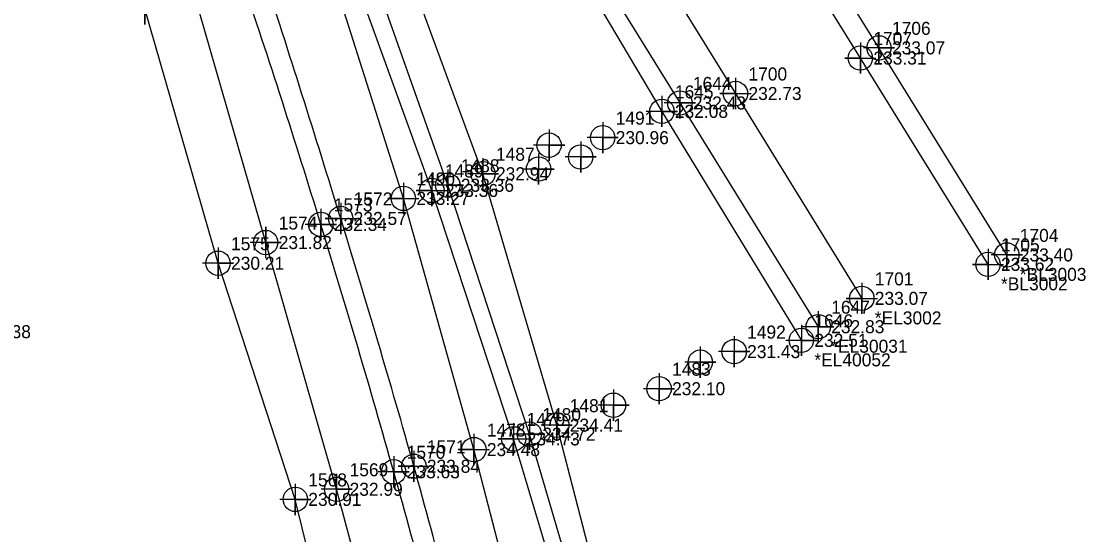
# Model space of a CAD drawing. Extents: x 2130962 to 2131465, y 643052 to 644206.
# Drawn here: x 2131080.2 to 2131285, y 643795.8 to 643894.5 of the extents above; entities that cross this region are included whole.
import ezdxf

# ---------------------------------------------------------------- set-up
doc = ezdxf.new("R2010")
doc.units = 0
for name, color, linetype in [('Exist DTM Breakline', 7, 'Continuous'), ('Exist DTM Breakline Cogo Comment', 7, 'Continuous'), ('Exist DTM Breakline Cogo Elevation', 7, 'Continuous'), ('Exist DTM Breakline Cogo Number', 7, 'Continuous'), ('Exist DTM Breakline Cogo Point CELL', 7, 'Continuous'), ('Exist DTM Drainline', 7, 'Continuous'), ('Exist DTM Drainline Cogo Elevation', 7, 'Continuous'), ('Exist DTM Drainline Cogo Number', 7, 'Continuous'), ('Exist DTM Drainline Cogo Point CELL', 7, 'Continuous'), ('Exist DTM Regular Point CELL', 7, 'Continuous'), ('Exist DTM Regular Point Cogo Elevation', 7, 'Continuous'), ('Exist DTM Regular Point Cogo Number', 7, 'Continuous'), ('Exist Roads EOP', 7, 'Continuous'), ('Exist Roads EOP Cogo Elevation', 7, 'Continuous'), ('Exist Roads EOP Cogo Number', 7, 'Continuous'), ('Exist Roads EOP Cogo Point CELL', 7, 'Continuous'), ('Exist Roads EOP Other Cogo Comment', 7, 'Continuous'), ('Exist Roads EOP Other Cogo Elevation', 7, 'Continuous'), ('Exist Roads EOP Other Cogo Number', 7, 'Continuous'), ('Exist Roads EOP Other Cogo Point CELL', 7, 'Continuous'), ('Exist Roads EOT', 7, 'Continuous'), ('Exist Roads EOT Cogo Comment', 7, 'Continuous'), ('Exist Roads EOT Cogo Elevation', 7, 'Continuous'), ('Exist Roads EOT Cogo Number', 7, 'Continuous'), ('Exist Roads EOT Cogo Point CELL', 7, 'Continuous'), ('Exist Roads Soil', 7, 'Continuous'), ('Exist Roads Soil Cogo Elevation', 7, 'Continuous'), ('Exist Roads Soil Cogo Number', 7, 'Continuous'), ('Exist Roads Soil Cogo Point CELL', 7, 'Continuous')]:
    doc.layers.add(name, color=color, linetype=linetype)

msp = doc.modelspace()

# ---------------------------------------------------------------- linework, layer by layer
at = {"layer": 'Exist DTM Breakline'}
for points in [[(2131266.3306, 643269.372), (2131264.0776, 643319.4437), (2131258.8396, 643369.5498), (2131255.3671, 643419.5794), (2131249.6414, 643469.556), (2131244.7652, 643520.0623), (2131238.8778, 643569.4077), (2131228.6495, 643620.6699), (2131219.85, 643669.4823), (2131206.9682, 643717.8453), (2131195.8132, 643768.1497), (2131183.2404, 643816.8151), (2131169.0496, 643865.1461), (2131151.2314, 643913.4424), (2131130.7295, 643958.9736), (2131122.7411, 643983.0115)], [(2131150.4586, 643966.3443), (2131176.896, 643921.8304), (2131203.4733, 643877.1362), (2131230.3046, 643833.1199)]]:
    msp.add_lwpolyline(points, dxfattribs=at)
at = {"layer": 'Exist DTM Breakline Cogo Point CELL'}
for points in [[(2131203.4733, 643880.1362), (2131203.4733, 643874.1362), (2131203.4733, 643877.1362), (2131206.4733, 643877.1362), (2131200.4733, 643877.1362)], [(2131169.0496, 643868.1461), (2131169.0496, 643862.1461), (2131169.0496, 643865.1461), (2131172.0496, 643865.1461), (2131166.0496, 643865.1461)], [(2131230.3046, 643836.1199), (2131230.3046, 643830.1199), (2131230.3046, 643833.1199), (2131233.3046, 643833.1199), (2131227.3046, 643833.1199)], [(2131183.2404, 643819.8151), (2131183.2404, 643813.8151), (2131183.2404, 643816.8151), (2131186.2404, 643816.8151), (2131180.2404, 643816.8151)]]:
    msp.add_lwpolyline(points, dxfattribs=at)
for centre in [(2131203.4733, 643877.1362), (2131169.0496, 643865.1461), (2131230.3046, 643833.1199), (2131183.2404, 643816.8151)]:
    msp.add_circle(centre, 2.344, dxfattribs=at)
at = {"layer": 'Exist DTM Drainline'}
msp.add_lwpolyline([(2131000.2029, 643226.7228), (2131050.9884, 643228.9032), (2131099.0297, 643228.5605), (2131120.2968, 643239.3591), (2131144.9156, 643253.3469), (2131146.4739, 643252.3674), (2131154.3188, 643256.8046), (2131168.9618, 643265.5132), (2131176.6257, 643272.964), (2131179.8144, 643285.303), (2131183.3842, 643315.022), (2131190.1471, 643365.8731), (2131190.1489, 643413.686), (2131192.3886, 643466.4632), (2131188.8083, 643512.615), (2131184.0059, 643563.7066), (2131175.3, 643610.7482), (2131168.3784, 643658.7431), (2131156.7476, 643707.4708), (2131144.9036, 643754.0458), (2131132.9438, 643802.544), (2131118.0831, 643847.9475), (2131104.0084, 643896.8663), (2131096.3866, 643919.4077)], dxfattribs=at)
at = {"layer": 'Exist DTM Drainline Cogo Point CELL'}
for points in [[(2131104.0084, 643899.8663), (2131104.0084, 643893.8663), (2131104.0084, 643896.8663), (2131107.0084, 643896.8663), (2131101.0084, 643896.8663)], [(2131118.0831, 643850.9475), (2131118.0831, 643844.9475), (2131118.0831, 643847.9475), (2131121.0831, 643847.9475), (2131115.0831, 643847.9475)], [(2131132.9438, 643805.544), (2131132.9438, 643799.544), (2131132.9438, 643802.544), (2131135.9438, 643802.544), (2131129.9438, 643802.544)]]:
    msp.add_lwpolyline(points, dxfattribs=at)
for centre in [(2131118.0831, 643847.9475), (2131132.9438, 643802.544)]:
    msp.add_circle(centre, 2.344, dxfattribs=at)
at = {"layer": 'Exist DTM Regular Point CELL'}
for points in [[(2131192.0852, 643875.0907), (2131192.0852, 643869.0907), (2131192.0852, 643872.0907), (2131195.0852, 643872.0907), (2131189.0852, 643872.0907)], [(2131181.7718, 643873.64), (2131181.7718, 643867.64), (2131181.7718, 643870.64), (2131184.7718, 643870.64), (2131178.7718, 643870.64)], [(2131187.8499, 643871.3759), (2131187.8499, 643865.3759), (2131187.8499, 643868.3759), (2131190.8499, 643868.3759), (2131184.8499, 643868.3759)], [(2131179.7469, 643869.0572), (2131179.7469, 643863.0572), (2131179.7469, 643866.0572), (2131182.7469, 643866.0572), (2131176.7469, 643866.0572)], [(2131217.3691, 643833.9559), (2131217.3691, 643827.9559), (2131217.3691, 643830.9559), (2131220.3691, 643830.9559), (2131214.3691, 643830.9559)], [(2131210.8569, 643831.9342), (2131210.8569, 643825.9342), (2131210.8569, 643828.9342), (2131213.8569, 643828.9342), (2131207.8569, 643828.9342)], [(2131202.9275, 643826.8229), (2131202.9275, 643820.8229), (2131202.9275, 643823.8229), (2131205.9275, 643823.8229), (2131199.9275, 643823.8229)], [(2131194.1553, 643823.6479), (2131194.1553, 643817.6479), (2131194.1553, 643820.6479), (2131197.1553, 643820.6479), (2131191.1553, 643820.6479)]]:
    msp.add_lwpolyline(points, dxfattribs=at)
for centre in [(2131181.7718, 643870.64), (2131192.0852, 643872.0907), (2131187.8499, 643868.3759), (2131179.7469, 643866.0572), (2131217.3691, 643830.9559), (2131210.8569, 643828.9342), (2131202.9275, 643823.8229), (2131194.1553, 643820.6479)]:
    msp.add_circle(centre, 2.344, dxfattribs=at)
at = {"layer": 'Exist Roads EOP'}
for points in [[(2131269.8281, 643849.5438), (2131245.2333, 643889.3452), (2131216.1751, 643936.1301), (2131188.6585, 643980.6301), (2131160.5575, 644026.0233), (2131133.7706, 644069.3844), (2131106.5621, 644113.2921), (2131078.4587, 644158.6941), (2131052.1516, 644201.1049)], [(2131124.9979, 644001.4036), (2131151.4846, 643966.5856), (2131158.5905, 643957.1022), (2131179.4402, 643923.1833), (2131206.9257, 643878.7542), (2131233.5521, 643835.7453)], [(2131264.2715, 643222.5647), (2131259.8757, 643269.3254), (2131257.0196, 643319.4043), (2131254.2561, 643369.6499), (2131250.0777, 643419.4187), (2131246.1511, 643469.0294), (2131240.8382, 643519.1271), (2131234.3674, 643568.5584), (2131226.3321, 643620.1808), (2131217.0271, 643668.7116), (2131205.6213, 643717.607), (2131192.0578, 643767.2595), (2131177.9714, 643815.0911), (2131162.2913, 643862.9344), (2131145.3604, 643910.8486), (2131126.9113, 643957.2915), (2131112.3691, 643996.1228)]]:
    msp.add_lwpolyline(points, dxfattribs=at)
msp.add_spline([(2131166.2495, 643216.6951), (2131171.8131, 643218.7244), (2131182.3713, 643223.9726), (2131191.8117, 643231.1489), (2131200.5013, 643239.6993), (2131208.8071, 643249.0697), (2131216.0672, 643259.0032), (2131218.7188, 643264.347), (2131220.5363, 643270.0958), (2131222.8445, 643282.0077), (2131224.3583, 643293.9245), (2131224.8763, 643317.7904), (2131222.0632, 643367.6716), (2131218.5448, 643416.8114), (2131214.3187, 643466.3462), (2131209.1735, 643515.6666), (2131202.7939, 643565.1545), (2131195.0475, 643613.9937), (2131186.4014, 643662.4763), (2131176.0113, 643711.405), (2131164.6154, 643759.8896), (2131151.874, 643807.8526), (2131137.8554, 643855.4065), (2131122.5733, 643902.8574), (2131105.9622, 643949.4862), (2131091.5349, 643988.0437)], degree=3, dxfattribs=at)
at = {"layer": 'Exist Roads EOP Cogo Point CELL'}
for points in [[(2131162.2913, 643865.9344), (2131162.2913, 643859.9344), (2131162.2913, 643862.9344), (2131165.2913, 643862.9344), (2131159.2913, 643862.9344)], [(2131137.8554, 643858.4065), (2131137.8554, 643852.4065), (2131137.8554, 643855.4065), (2131140.8554, 643855.4065), (2131134.8554, 643855.4065)], [(2131177.9714, 643818.0911), (2131177.9714, 643812.0911), (2131177.9714, 643815.0911), (2131180.9714, 643815.0911), (2131174.9714, 643815.0911)], [(2131151.874, 643810.8526), (2131151.874, 643804.8526), (2131151.874, 643807.8526), (2131154.874, 643807.8526), (2131148.874, 643807.8526)]]:
    msp.add_lwpolyline(points, dxfattribs=at)
for centre in [(2131162.2913, 643862.9344), (2131137.8554, 643855.4065), (2131177.9714, 643815.0911), (2131151.874, 643807.8526)]:
    msp.add_circle(centre, 2.344, dxfattribs=at)
at = {"layer": 'Exist Roads EOP Other Cogo Point CELL'}
for points in [[(2131245.2333, 643892.3452), (2131245.2333, 643886.3452), (2131245.2333, 643889.3452), (2131248.2333, 643889.3452), (2131242.2333, 643889.3452)], [(2131206.9257, 643881.7542), (2131206.9257, 643875.7542), (2131206.9257, 643878.7542), (2131209.9257, 643878.7542), (2131203.9257, 643878.7542)], [(2131269.8281, 643852.5438), (2131269.8281, 643846.5438), (2131269.8281, 643849.5438), (2131272.8281, 643849.5438), (2131266.8281, 643849.5438)], [(2131233.5521, 643838.7453), (2131233.5521, 643832.7453), (2131233.5521, 643835.7453), (2131236.5521, 643835.7453), (2131230.5521, 643835.7453)]]:
    msp.add_lwpolyline(points, dxfattribs=at)
for centre in [(2131245.2333, 643889.3452), (2131206.9257, 643878.7542), (2131269.8281, 643849.5438), (2131233.5521, 643835.7453)]:
    msp.add_circle(centre, 2.344, dxfattribs=at)
at = {"layer": 'Exist Roads EOT'}
for points in [[(2131266.2139, 643847.7337), (2131241.6557, 643887.3896), (2131212.415, 643934.4728), (2131185.0265, 643979.1763), (2131157.0131, 644024.017), (2131130.1473, 644067.7247), (2131102.8992, 644111.8313), (2131074.9921, 644156.7275), (2131048.5158, 644199.6357)], [(2131027.1782, 644188.3908), (2131054.4288, 644144.4752), (2131080.5567, 644102.0812), (2131108.007, 644057.7457), (2131134.6373, 644014.7205), (2131162.4421, 643969.638), (2131189.8746, 643925.4695), (2131217.6277, 643880.5724), (2131241.9317, 643841.1922)], [(2131255.7894, 643269.2666), (2131252.7511, 643319.2443), (2131249.9083, 643369.5477), (2131246.3502, 643419.1778), (2131242.1933, 643468.6938), (2131237.0867, 643518.9193), (2131230.8671, 643568.2588), (2131222.7066, 643619.1047), (2131213.6442, 643668.3078), (2131202.755, 643717.0933), (2131189.234, 643766.4577), (2131174.9499, 643814.1787), (2131159.2111, 643861.933), (2131141.9103, 643909.6722), (2131123.7008, 643956.0828), (2131104.9436, 644003.1503), (2131086.2706, 644048.8072), (2131065.6997, 644094.9191), (2131044.3618, 644140.0645), (2131021.6804, 644185.4526)], [(2131237.6994, 643363.706), (2131234.1644, 643418.0043), (2131229.8934, 643468.0098), (2131225.1139, 643518.3873), (2131218.7748, 643566.6133), (2131210.7043, 643617.3811), (2131201.4139, 643666.7928), (2131191.4121, 643714.0755), (2131179.6696, 643764.3904), (2131167.3006, 643812.1237), (2131153.7359, 643860.4033), (2131138.3711, 643908.8544), (2131125.1607, 643951.4161)]]:
    msp.add_lwpolyline(points, dxfattribs=at)
msp.add_spline([(2131166.718, 643215.2083), (2131172.3866, 643217.1804), (2131211.4056, 643247.1499), (2131223.758, 643268.7314), (2131228.3848, 643317.935), (2131225.533, 643367.8628), (2131222.2486, 643417.1873), (2131217.9619, 643466.6275), (2131212.8794, 643516.2377), (2131206.5633, 643565.5764), (2131198.9021, 643614.6757), (2131189.6851, 643663.4055), (2131179.3985, 643712.1311), (2131168.3085, 643760.7185), (2131155.755, 643808.9129), (2131141.6748, 643856.5528), (2131126.5354, 643904.2758), (2131110.3559, 643951.0191), (2131092.4533, 643998.1348), (2131073.722, 644043.631), (2131053.1654, 644089.359), (2131032.0052, 644134.0908), (2131009.0644, 644179.3802)], degree=3, dxfattribs=at)
at = {"layer": 'Exist Roads EOT Cogo Point CELL'}
for points in [[(2131241.6557, 643890.3896), (2131241.6557, 643884.3896), (2131241.6557, 643887.3896), (2131238.6557, 643887.3896), (2131244.6557, 643887.3896)], [(2131217.6277, 643883.5724), (2131217.6277, 643877.5724), (2131217.6277, 643880.5724), (2131214.6277, 643880.5724), (2131220.6277, 643880.5724)], [(2131159.2111, 643864.933), (2131159.2111, 643858.933), (2131159.2111, 643861.933), (2131156.2111, 643861.933), (2131162.2111, 643861.933)], [(2131153.7359, 643863.4033), (2131153.7359, 643857.4033), (2131153.7359, 643860.4033), (2131150.7359, 643860.4033), (2131156.7359, 643860.4033)], [(2131141.6748, 643859.5528), (2131141.6748, 643853.5528), (2131141.6748, 643856.5528), (2131138.6748, 643856.5528), (2131144.6748, 643856.5528)], [(2131266.2139, 643850.7337), (2131266.2139, 643844.7337), (2131266.2139, 643847.7337), (2131263.2139, 643847.7337), (2131269.2139, 643847.7337)], [(2131241.9317, 643844.1922), (2131241.9317, 643838.1922), (2131241.9317, 643841.1922), (2131238.9317, 643841.1922), (2131244.9317, 643841.1922)], [(2131174.9499, 643817.1787), (2131174.9499, 643811.1787), (2131174.9499, 643814.1787), (2131171.9499, 643814.1787), (2131177.9499, 643814.1787)], [(2131167.3006, 643815.1237), (2131167.3006, 643809.1237), (2131167.3006, 643812.1237), (2131164.3006, 643812.1237), (2131170.3006, 643812.1237)], [(2131155.755, 643811.9129), (2131155.755, 643805.9129), (2131155.755, 643808.9129), (2131152.755, 643808.9129), (2131158.755, 643808.9129)]]:
    msp.add_lwpolyline(points, dxfattribs=at)
for centre in [(2131241.6557, 643887.3896), (2131217.6277, 643880.5724), (2131159.2111, 643861.933), (2131153.7359, 643860.4033), (2131141.6748, 643856.5528), (2131266.2139, 643847.7337), (2131241.9317, 643841.1922), (2131174.9499, 643814.1787), (2131167.3006, 643812.1237), (2131155.755, 643808.9129)]:
    msp.add_circle(centre, 2.344, dxfattribs=at)
at = {"layer": 'Exist Roads Soil'}
msp.add_lwpolyline([(2131224.8674, 643317.753), (2131220.141, 643317.6487), (2131216.7544, 643367.544), (2131211.084, 643416.163), (2131207.4344, 643466.363), (2131202.1097, 643514.7948), (2131195.0195, 643564.3052), (2131187.2605, 643612.6498), (2131179.506, 643660.9545), (2131164.8317, 643709.0781), (2131153.9175, 643755.9834), (2131140.8896, 643804.492), (2131127.2512, 643851.9231), (2131113.4771, 643899.8082), (2131083.6685, 643994.997), (2131066.191, 644040.9476), (2131049.1539, 644087.3869)], dxfattribs=at)
at = {"layer": 'Exist Roads Soil Cogo Point CELL'}
for points in [[(2131127.2512, 643848.9231), (2131127.2512, 643854.9231), (2131127.2512, 643851.9231), (2131130.2512, 643851.9231), (2131124.2512, 643851.9231)], [(2131140.8896, 643801.492), (2131140.8896, 643807.492), (2131140.8896, 643804.492), (2131143.8896, 643804.492), (2131137.8896, 643804.492)]]:
    msp.add_lwpolyline(points, dxfattribs=at)
for centre in [(2131127.2512, 643851.9231), (2131140.8896, 643804.492)]:
    msp.add_circle(centre, 2.344, dxfattribs=at)

# ---------------------------------------------------------------- texts
at = {"layer": 'Exist DTM Breakline Cogo Comment'}
msp.add_text('*EL40052', height=2.5, dxfattribs=at).set_placement((2131232.8046, 643828.1199))
at = {"layer": 'Exist DTM Breakline Cogo Elevation'}
for s, p in [('232.08', (2131205.9733, 643875.8862)), ('232.94', (2131171.5496, 643863.8961)), ('252.38', (2131071.8516, 643833.5464)), ('232.51', (2131232.8046, 643831.8699)), ('234.41', (2131185.7404, 643815.5651))]:
    msp.add_text(s, height=2.5, dxfattribs=at).set_placement(p)
at = {"layer": 'Exist DTM Breakline Cogo Number'}
for s, p in [('1645', (2131205.9733, 643879.6362)), ('1487', (2131171.5496, 643867.6461)), ('1646', (2131232.8046, 643835.6199)), ('1481', (2131185.7404, 643819.3151))]:
    msp.add_text(s, height=2.5, dxfattribs=at).set_placement(p)
at = {"layer": 'Exist DTM Drainline Cogo Elevation'}
for s, p in [('230.21', (2131120.5831, 643846.6975)), ('230.91', (2131135.4438, 643801.294))]:
    msp.add_text(s, height=2.5, dxfattribs=at).set_placement(p)
at = {"layer": 'Exist DTM Drainline Cogo Number'}
for s, p in [('1575', (2131120.5831, 643850.4475)), ('1568', (2131135.4438, 643805.044))]:
    msp.add_text(s, height=2.5, dxfattribs=at).set_placement(p)
at = {"layer": 'Exist DTM Regular Point Cogo Elevation'}
for s, p in [('230.96', (2131194.5852, 643870.8407)), ('231.43', (2131219.8691, 643829.7059)), ('232.10', (2131205.4275, 643822.5729))]:
    msp.add_text(s, height=2.5, dxfattribs=at).set_placement(p)
at = {"layer": 'Exist DTM Regular Point Cogo Number'}
for s, p in [('1491', (2131194.5852, 643874.5907)), ('1492', (2131219.8691, 643833.4559)), ('1483', (2131205.4275, 643826.3229))]:
    msp.add_text(s, height=2.5, dxfattribs=at).set_placement(p)
at = {"layer": 'Exist Roads EOP Cogo Elevation'}
for s, p in [('233.36', (2131164.7913, 643861.6844)), ('232.34', (2131140.3554, 643854.1565)), ('234.72', (2131180.4714, 643813.8411)), ('233.63', (2131154.374, 643806.6026))]:
    msp.add_text(s, height=2.5, dxfattribs=at).set_placement(p)
at = {"layer": 'Exist Roads EOP Cogo Number'}
for s, p in [('1488', (2131164.7913, 643865.4344)), ('1573', (2131140.3554, 643857.9065)), ('1480', (2131180.4714, 643817.5911)), ('1570', (2131154.374, 643810.3526))]:
    msp.add_text(s, height=2.5, dxfattribs=at).set_placement(p)
at = {"layer": 'Exist Roads EOP Other Cogo Comment'}
for s, p in [('*BL3003', (2131272.3281, 643844.5438)), ('*EL30031', (2131236.0521, 643830.7453))]:
    msp.add_text(s, height=2.5, dxfattribs=at).set_placement(p)
at = {"layer": 'Exist Roads EOP Other Cogo Elevation'}
for s, p in [('233.07', (2131247.7333, 643888.0952)), ('232.43', (2131209.4257, 643877.5042)), ('233.40', (2131272.3281, 643848.2938)), ('232.83', (2131236.0521, 643834.4953))]:
    msp.add_text(s, height=2.5, dxfattribs=at).set_placement(p)
at = {"layer": 'Exist Roads EOP Other Cogo Number'}
for s, p in [('1706', (2131247.7333, 643891.8452)), ('1644', (2131209.4257, 643881.2542)), ('1704', (2131272.3281, 643852.0438)), ('1647', (2131236.0521, 643838.2453))]:
    msp.add_text(s, height=2.5, dxfattribs=at).set_placement(p)
at = {"layer": 'Exist Roads EOT Cogo Comment'}
for s, p in [('*BL3002', (2131268.7139, 643842.7337)), ('*EL3002', (2131244.4317, 643836.1922))]:
    msp.add_text(s, height=2.5, dxfattribs=at).set_placement(p)
at = {"layer": 'Exist Roads EOT Cogo Elevation'}
for s, p in [('233.31', (2131244.1557, 643886.1396)), ('232.73', (2131220.1277, 643879.3224)), ('233.36', (2131161.7111, 643860.683)), ('233.27', (2131156.2359, 643859.1533)), ('232.57', (2131144.1748, 643855.3028)), ('233.62', (2131268.7139, 643846.4837)), ('233.07', (2131244.4317, 643839.9422)), ('234.73', (2131177.4499, 643812.9287)), ('234.48', (2131169.8006, 643810.8737)), ('233.84', (2131158.255, 643807.6629))]:
    msp.add_text(s, height=2.5, dxfattribs=at).set_placement(p)
at = {"layer": 'Exist Roads EOT Cogo Number'}
for s, p in [('1707', (2131244.1557, 643889.8896)), ('1700', (2131220.1277, 643883.0724)), ('1489', (2131161.7111, 643864.433)), ('1490', (2131156.2359, 643862.9033)), ('1572', (2131144.1748, 643859.0528)), ('1705', (2131268.7139, 643850.2337)), ('1701', (2131244.4317, 643843.6922)), ('1479', (2131177.4499, 643816.6787)), ('1478', (2131169.8006, 643814.6237)), ('1571', (2131158.255, 643811.4129))]:
    msp.add_text(s, height=2.5, dxfattribs=at).set_placement(p)
at = {"layer": 'Exist Roads Soil Cogo Elevation'}
for s, p in [('231.82', (2131129.7512, 643850.6731)), ('232.99', (2131143.3896, 643803.242))]:
    msp.add_text(s, height=2.5, dxfattribs=at).set_placement(p)
at = {"layer": 'Exist Roads Soil Cogo Number'}
for s, p in [('1574', (2131129.7512, 643854.4231)), ('1569', (2131143.3896, 643806.992))]:
    msp.add_text(s, height=2.5, dxfattribs=at).set_placement(p)

doc.saveas('drawing.dxf')
